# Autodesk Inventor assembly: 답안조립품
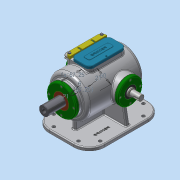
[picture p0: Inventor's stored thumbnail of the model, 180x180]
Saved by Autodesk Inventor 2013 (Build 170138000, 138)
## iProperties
Created: 2019-10
Part Number: 답안조립품
Document SubType Name: Assembly
Designer: Administrator
Mass: 7821.82 g
Surface Area: 4928.07 cm^2
Volume: 2176.15 cm^3
Density: 3.59434 g/cm^3
Author: Administrator
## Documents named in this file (17)
- C:\Users\Administrator\Desktop\391004V1036\답안조립품.iam
- C:\Users\Administrator\Desktop\391004V1036\본체.ipt
- C:\Users\Administrator\Desktop\391004V1036\가변스프링.ipt
- C:\Users\Administrator\Desktop\391004V1036\개스킷 A.ipt
- C:\Users\Administrator\Desktop\391004V1036\개스킷 B.ipt
- C:\Users\Administrator\Desktop\391004V1036\고정플레이트.ipt
- C:\Users\Administrator\Desktop\391004V1036\베어링 6205.ipt
- 베어링 6205.ipt
- C:\Users\Administrator\Desktop\391004V1036\볼트 M4x0.7.ipt
- C:\Users\Administrator\Desktop\391004V1036\부시.ipt
- C:\Users\Administrator\Desktop\391004V1036\상부커버.ipt
- C:\Users\Administrator\Desktop\391004V1036\슬라이드 커버.ipt
- C:\Users\Administrator\Desktop\391004V1036\슬라이드.ipt
- C:\Users\Administrator\Desktop\391004V1036\오일 실 25 38 8.ipt
- C:\Users\Administrator\Desktop\391004V1036\육각머리볼트 M4.ipt
- C:\Users\Administrator\Desktop\391004V1036\축 커버.ipt
- C:\Users\Administrator\Desktop\391004V1036\편심축.ipt
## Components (17 placed, 5 different names)
1. 개스킷 A:1
2. 개스킷 B:1
3. 고정플레이트:1 — 플러쉬:1
4. 개스킷 B:2
5. 가변스프링:1
6. M4x0.7:2
7. M4x0.7:3
8. M4x0.7:4
9. M4x0.7:5
10. M4x0.7:1
11. M4x0.7:6
12. M4x0.7:7
13. M4x0.7:8
14. M4x0.7:9
15. M4x0.7:10
16. M4x0.7:11
17. M4x0.7:12
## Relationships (1: Flush 1)
- 플러쉬:1 [Flush]: 고정플레이트:1
